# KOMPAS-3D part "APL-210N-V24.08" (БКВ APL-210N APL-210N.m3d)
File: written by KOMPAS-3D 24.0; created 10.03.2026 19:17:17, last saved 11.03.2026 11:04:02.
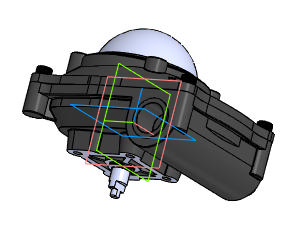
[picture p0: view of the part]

Document properties: Автор: R2D2; Полное имя файла: E:\Работа\Зайцев\БКВ APL-210N Блок концевых выключателей DN.ru\исходные материалы\БКВ APL-210N APL-210N.m3d

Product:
- Body: NONE  | qty 1  | 2 such rows
    Масса: 0.000427
- Body: NONE  | qty 1  | 4 such rows
    Масса: 0.004368
- Body: NONE  | qty 1  | 2 such rows
    Масса: 0.00851
- Body: NONE  | qty 1
    Масса: 0.000172
- Body: NONE  | qty 1
    Масса: 0.066061
- Body: NONE  | qty 1
    Масса: 0.001143
- Body: NONE  | qty 1
    Масса: 1.455769
- Body: NONE  | qty 1
    Масса: 0.010465
- Body: NONE  | qty 1
    Масса: 0.031232
- Body: NONE  | qty 1
    Масса: 0.010936
- Body: NONE  | qty 1
    Масса: 0.082245
- Body: NONE  | qty 1
    Масса: 0.0005
- Body: NONE  | qty 1
    Масса: 0.443903
- Part/product: APL-210N-V24.08
    Масса: 2.129262

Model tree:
1. NONE
2. Эскиз:1
3. Элемент выдавливания:1
     Расстояние 2 = 1
4. Эскиз:2
5. Элемент выдавливания:2
     Расстояние 2 = 1
6. Элемент выдавливания:3
     Расстояние 2 = 1
7. Эскиз:3
8. Элемент выдавливания:4
     Расстояние 2 = 1
9. Эскиз:4
10. Элемент вращения:2
     Угол 1 = 360
11. Эскиз:7
12. Элемент выдавливания:6
     Расстояние 1 = 30
13. Эскиз:8  (with: Ребро.Элемент выдавливания:4)
14. Элемент вращения:4
     Угол 1 = 360
15. Эскиз:9  (with: Грань.Элемент вращения:4)
16. Элемент выдавливания:7
     Расстояние 2 = 8
17. Фаска:1  (with: Ребро.Элемент вращения:4)
     Угол = 45; Длина 1 = 0.5; Длина 2 = 0.5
